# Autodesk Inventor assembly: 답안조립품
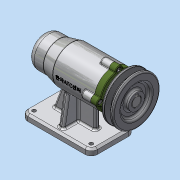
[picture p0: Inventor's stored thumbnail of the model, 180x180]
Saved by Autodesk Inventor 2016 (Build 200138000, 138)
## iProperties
Created: 2019-07
Part Number: 답안조립품
Material: 일반
Document SubType Name: Assembly
Designer: Administrator
Author: Administrator
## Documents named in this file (12)
- C:\Users\Administrator\Desktop\490704V1006\답안조립품.iam
- C:\Users\Administrator\Desktop\490704V1006\본체.ipt
- C:\Users\Administrator\Desktop\490704V1006\커버.ipt
- C:\Users\Administrator\Desktop\490704V1006\베어링 51202.ipt
- C:\Users\Administrator\Desktop\490704V1006\베어링 6004.ipt
- C:\Users\Administrator\Desktop\490704V1006\축.ipt
- C:\Users\Administrator\Desktop\490704V1006\어댑터슬리브.ipt
- C:\Users\Administrator\Desktop\490704V1006\볼트 M4.ipt
- C:\Users\Administrator\Desktop\490704V1006\키 5 x 5 x 16.ipt
- C:\Users\Administrator\Desktop\490704V1006\V벨트풀리.ipt
- C:\Users\Administrator\Desktop\490704V1006\오일 실.ipt
- C:\Users\Administrator\Desktop\490704V1006\멈춤나사 M3.ipt
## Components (1 placed, 1 different names)
1. V벨트풀리:1
